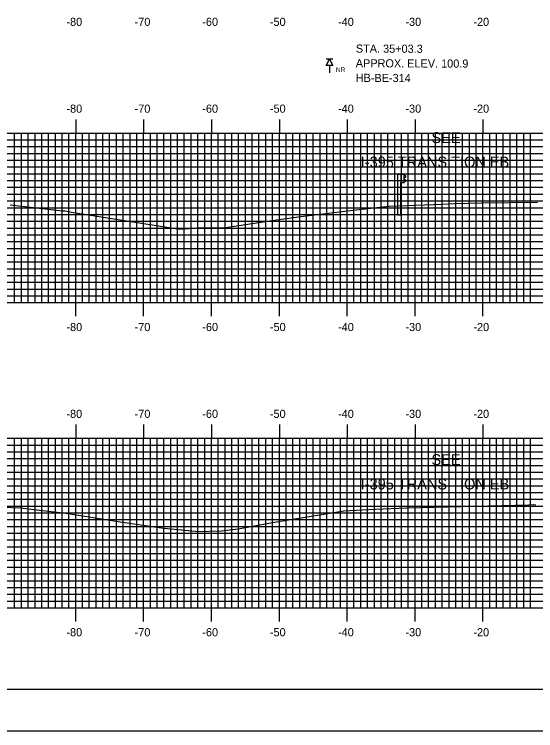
# Model space of a CAD drawing. Extents: x 842962 to 843305, y 363538 to 363758.
# Drawn here: x 843038.9 to 843115.7, y 363537.6 to 363643.2 of the extents above; entities that cross this region are included whole.
import ezdxf

# ---------------------------------------------------------------- set-up
doc = ezdxf.new("R2010")
doc.units = 0
for name, color, linetype in [('ANNOTATION', 7, 'Continuous'), ('BORDER', 7, 'Continuous'), ('BORING - NO REFUSAL', 7, 'Continuous'), ('H_V ANNOTATION', 7, 'Continuous'), ('M_Guardrail', 7, 'Continuous'), ('M_Roadway_Centerline', 7, 'Continuous'), ('MAJOR', 7, 'Continuous'), ('MINOR', 7, 'Continuous'), ('PLOT BOUNDARY', 7, 'Continuous'), ('S_Roadway_Centerline', 7, 'Continuous')]:
    doc.layers.add(name, color=color, linetype=linetype)

msp = doc.modelspace()

# ---------------------------------------------------------------- linework, layer by layer
at = {"layer": 'BORDER'}
msp.add_lwpolyline([(842978.31, 363543.72), (843298.31, 363543.72), (843298.31, 363753.72), (842978.31, 363753.72)], close=True, dxfattribs=at)
at = {"layer": 'BORING - NO REFUSAL'}
for p, q in [((843085.79, 363636.62), (843084.83, 363636.62)), ((843085.31, 363635.66), (843085.31, 363634.6))]:
    msp.add_line(p, q, dxfattribs=at)
msp.add_lwpolyline([(843085.31, 363636.62), (843085.79, 363635.66), (843084.83, 363635.66)], close=True, dxfattribs=at)
at = {"layer": 'M_Guardrail'}
for p, q in [((843095.3, 363619.6), (843095.3, 363613.6)), ((843095.79, 363619.6), (843095.3, 363619.6)), ((843096.28, 363619.6), (843095.79, 363619.6)), ((843095.79, 363619.6), (843095.79, 363618.44)), ((843096.28, 363618.44), (843096.28, 363619.6)), ((843096.28, 363619.53), (843096.37, 363619.52)), ((843096.53, 363619.27), (843096.33, 363619.13)), ((843096.38, 363619.51), (843096.53, 363619.41)), ((843095.79, 363613.6), (843095.79, 363618.44)), ((843095.79, 363618.44), (843096.28, 363618.44)), ((843096.37, 363618.53), (843096.28, 363618.51)), ((843096.3, 363619.07), (843096.3, 363618.98)), ((843096.33, 363618.91), (843096.53, 363618.78)), ((843096.53, 363618.63), (843096.38, 363618.53)), ((843095.79, 363613.6), (843095.3, 363613.6))]:
    msp.add_line(p, q, dxfattribs=at)
for centre, major_axis, start_param, end_param in [((843096.38, 363619.07), (-0.0789, 0), 5.323254, 6.283185), ((843096.36, 363619.48), (0.0417, 0), 0.959931, 1.396263), ((843096.48, 363619.34), (0.0877, 0), 5.323254, 7.243116), ((843096.38, 363618.98), (-0.0789, 0), 6.283185, 7.243116), ((843096.36, 363618.57), (0.0417, 0), 4.886922, 5.323254), ((843096.48, 363618.7), (0.0877, 0), 5.323254, 7.243116)]:
    msp.add_ellipse(centre, major_axis=major_axis, ratio=0.995501, start_param=start_param, end_param=end_param, dxfattribs=at)
at = {"layer": 'MAJOR'}
for p, q in [((843047.91, 363627.73), (843047.91, 363625.72)), ((843057.91, 363627.73), (843057.91, 363625.72)), ((843067.91, 363627.73), (843067.91, 363625.72)), ((843077.91, 363627.73), (843077.91, 363625.72)), ((843087.91, 363627.73), (843087.91, 363625.72)), ((843097.91, 363627.73), (843097.91, 363625.72)), ((843107.91, 363627.73), (843107.91, 363625.72)), ((842987.91, 363625.72), (843267.91, 363625.72)), ((842987.91, 363625.72), (843267.91, 363625.72)), ((843047.91, 363600.72), (843047.91, 363625.72)), ((843057.91, 363600.72), (843057.91, 363625.72)), ((843067.91, 363600.72), (843067.91, 363625.72)), ((843077.91, 363600.72), (843077.91, 363625.72)), ((843087.91, 363600.72), (843087.91, 363625.72)), ((843097.91, 363600.72), (843097.91, 363625.72)), ((843107.91, 363600.72), (843107.91, 363625.72)), ((842987.91, 363620.72), (843267.91, 363620.72)), ((842987.91, 363615.72), (843267.91, 363615.72)), ((842987.91, 363610.72), (843267.91, 363610.72)), ((842987.91, 363605.72), (843267.91, 363605.72)), ((842987.91, 363600.72), (843267.91, 363600.72)), ((842987.91, 363600.72), (843267.91, 363600.72)), ((843047.91, 363598.72), (843047.91, 363600.72)), ((843057.91, 363598.72), (843057.91, 363600.72)), ((843067.91, 363598.72), (843067.91, 363600.72)), ((843077.91, 363598.72), (843077.91, 363600.72)), ((843087.91, 363598.72), (843087.91, 363600.72)), ((843097.91, 363598.72), (843097.91, 363600.72)), ((843107.91, 363598.72), (843107.91, 363600.72)), ((843047.91, 363582.73), (843047.91, 363580.72)), ((843057.91, 363582.73), (843057.91, 363580.72)), ((843067.91, 363582.73), (843067.91, 363580.72)), ((843077.91, 363582.73), (843077.91, 363580.72)), ((843087.91, 363582.73), (843087.91, 363580.72)), ((843097.91, 363582.73), (843097.91, 363580.72)), ((843107.91, 363582.73), (843107.91, 363580.72)), ((842987.91, 363580.72), (843267.91, 363580.72)), ((842987.91, 363580.72), (843267.91, 363580.72)), ((843047.91, 363555.72), (843047.91, 363580.72)), ((843057.91, 363555.72), (843057.91, 363580.72)), ((843067.91, 363555.72), (843067.91, 363580.72)), ((843077.91, 363555.72), (843077.91, 363580.72)), ((843087.91, 363555.72), (843087.91, 363580.72)), ((843097.91, 363555.72), (843097.91, 363580.72)), ((843107.91, 363555.72), (843107.91, 363580.72)), ((842987.91, 363575.72), (843267.91, 363575.72)), ((842987.91, 363570.72), (843267.91, 363570.72)), ((842987.91, 363565.72), (843267.91, 363565.72)), ((842987.91, 363560.72), (843267.91, 363560.72)), ((842987.91, 363555.72), (843267.91, 363555.72)), ((842987.91, 363555.72), (843267.91, 363555.72)), ((843047.91, 363553.72), (843047.91, 363555.72)), ((843057.91, 363553.72), (843057.91, 363555.72)), ((843067.91, 363553.72), (843067.91, 363555.72)), ((843077.91, 363553.72), (843077.91, 363555.72)), ((843087.91, 363553.72), (843087.91, 363555.72)), ((843097.91, 363553.72), (843097.91, 363555.72)), ((843107.91, 363553.72), (843107.91, 363555.72))]:
    msp.add_line(p, q, dxfattribs=at)
at = {"layer": 'MINOR'}
for p, q in [((843038.91, 363600.72), (843038.91, 363625.72)), ((843039.91, 363600.72), (843039.91, 363625.72)), ((843040.91, 363600.72), (843040.91, 363625.72)), ((843041.91, 363600.72), (843041.91, 363625.72)), ((843042.91, 363600.72), (843042.91, 363625.72)), ((843043.91, 363600.72), (843043.91, 363625.72)), ((843044.91, 363600.72), (843044.91, 363625.72)), ((843045.91, 363600.72), (843045.91, 363625.72)), ((843046.91, 363600.72), (843046.91, 363625.72)), ((843048.91, 363600.72), (843048.91, 363625.72)), ((843049.91, 363600.72), (843049.91, 363625.72)), ((843050.91, 363600.72), (843050.91, 363625.72)), ((843051.91, 363600.72), (843051.91, 363625.72)), ((843052.91, 363600.72), (843052.91, 363625.72)), ((843053.91, 363600.72), (843053.91, 363625.72)), ((843054.91, 363600.72), (843054.91, 363625.72)), ((843055.91, 363600.72), (843055.91, 363625.72)), ((843056.91, 363600.72), (843056.91, 363625.72)), ((843058.91, 363600.72), (843058.91, 363625.72)), ((843059.91, 363600.72), (843059.91, 363625.72)), ((843060.91, 363600.72), (843060.91, 363625.72)), ((843061.91, 363600.72), (843061.91, 363625.72)), ((843062.91, 363600.72), (843062.91, 363625.72)), ((843063.91, 363600.72), (843063.91, 363625.72)), ((843064.91, 363600.72), (843064.91, 363625.72)), ((843065.91, 363600.72), (843065.91, 363625.72)), ((843066.91, 363600.72), (843066.91, 363625.72)), ((843068.91, 363600.72), (843068.91, 363625.72)), ((843069.91, 363600.72), (843069.91, 363625.72)), ((843070.91, 363600.72), (843070.91, 363625.72)), ((843071.91, 363600.72), (843071.91, 363625.72)), ((843072.91, 363600.72), (843072.91, 363625.72)), ((843073.91, 363600.72), (843073.91, 363625.72)), ((843074.91, 363600.72), (843074.91, 363625.72)), ((843075.91, 363600.72), (843075.91, 363625.72)), ((843076.91, 363600.72), (843076.91, 363625.72)), ((843078.91, 363600.72), (843078.91, 363625.72)), ((843079.91, 363600.72), (843079.91, 363625.72)), ((843080.91, 363600.72), (843080.91, 363625.72)), ((843081.91, 363600.72), (843081.91, 363625.72)), ((843082.91, 363600.72), (843082.91, 363625.72)), ((843083.91, 363600.72), (843083.91, 363625.72)), ((843084.91, 363600.72), (843084.91, 363625.72)), ((843085.91, 363600.72), (843085.91, 363625.72)), ((843086.91, 363600.72), (843086.91, 363625.72)), ((843088.91, 363600.72), (843088.91, 363625.72)), ((843089.91, 363600.72), (843089.91, 363625.72)), ((843090.91, 363600.72), (843090.91, 363625.72)), ((843091.91, 363600.72), (843091.91, 363625.72)), ((843092.91, 363600.72), (843092.91, 363625.72)), ((843093.91, 363600.72), (843093.91, 363625.72)), ((843094.91, 363600.72), (843094.91, 363625.72)), ((843095.91, 363600.72), (843095.91, 363625.72)), ((843096.91, 363600.72), (843096.91, 363625.72)), ((843098.91, 363600.72), (843098.91, 363625.72)), ((843099.91, 363600.72), (843099.91, 363625.72)), ((843100.91, 363600.72), (843100.91, 363625.72)), ((843101.91, 363600.72), (843101.91, 363625.72)), ((843102.91, 363600.72), (843102.91, 363625.72)), ((843103.91, 363600.72), (843103.91, 363625.72)), ((843104.91, 363600.72), (843104.91, 363625.72)), ((843105.91, 363600.72), (843105.91, 363625.72)), ((843106.91, 363600.72), (843106.91, 363625.72)), ((843108.91, 363600.72), (843108.91, 363625.72)), ((843109.91, 363600.72), (843109.91, 363625.72)), ((843110.91, 363600.72), (843110.91, 363625.72)), ((843111.91, 363600.72), (843111.91, 363625.72)), ((843112.91, 363600.72), (843112.91, 363625.72)), ((843113.91, 363600.72), (843113.91, 363625.72)), ((843114.91, 363600.72), (843114.91, 363625.72)), ((842987.91, 363624.72), (843267.91, 363624.72)), ((842987.91, 363623.72), (843267.91, 363623.72)), ((842987.91, 363622.72), (843267.91, 363622.72)), ((842987.91, 363621.72), (843267.91, 363621.72)), ((842987.91, 363619.72), (843267.91, 363619.72)), ((842987.91, 363618.72), (843267.91, 363618.72)), ((842987.91, 363617.72), (843267.91, 363617.72)), ((842987.91, 363616.72), (843267.91, 363616.72)), ((842987.91, 363614.72), (843267.91, 363614.72)), ((842987.91, 363613.72), (843267.91, 363613.72)), ((842987.91, 363612.72), (843267.91, 363612.72)), ((842987.91, 363611.72), (843267.91, 363611.72)), ((842987.91, 363609.72), (843267.91, 363609.72)), ((842987.91, 363608.72), (843267.91, 363608.72)), ((842987.91, 363607.72), (843267.91, 363607.72)), ((842987.91, 363606.72), (843267.91, 363606.72)), ((842987.91, 363604.72), (843267.91, 363604.72)), ((842987.91, 363603.72), (843267.91, 363603.72)), ((842987.91, 363602.72), (843267.91, 363602.72)), ((842987.91, 363601.72), (843267.91, 363601.72)), ((843038.91, 363555.72), (843038.91, 363580.72)), ((843039.91, 363555.72), (843039.91, 363580.72)), ((843040.91, 363555.72), (843040.91, 363580.72)), ((843041.91, 363555.72), (843041.91, 363580.72)), ((843042.91, 363555.72), (843042.91, 363580.72)), ((843043.91, 363555.72), (843043.91, 363580.72)), ((843044.91, 363555.72), (843044.91, 363580.72)), ((843045.91, 363555.72), (843045.91, 363580.72)), ((843046.91, 363555.72), (843046.91, 363580.72)), ((843048.91, 363555.72), (843048.91, 363580.72)), ((843049.91, 363555.72), (843049.91, 363580.72)), ((843050.91, 363555.72), (843050.91, 363580.72)), ((843051.91, 363555.72), (843051.91, 363580.72)), ((843052.91, 363555.72), (843052.91, 363580.72)), ((843053.91, 363555.72), (843053.91, 363580.72)), ((843054.91, 363555.72), (843054.91, 363580.72)), ((843055.91, 363555.72), (843055.91, 363580.72)), ((843056.91, 363555.72), (843056.91, 363580.72)), ((843058.91, 363555.72), (843058.91, 363580.72)), ((843059.91, 363555.72), (843059.91, 363580.72)), ((843060.91, 363555.72), (843060.91, 363580.72)), ((843061.91, 363555.72), (843061.91, 363580.72)), ((843062.91, 363555.72), (843062.91, 363580.72)), ((843063.91, 363555.72), (843063.91, 363580.72)), ((843064.91, 363555.72), (843064.91, 363580.72)), ((843065.91, 363555.72), (843065.91, 363580.72)), ((843066.91, 363555.72), (843066.91, 363580.72)), ((843068.91, 363555.72), (843068.91, 363580.72)), ((843069.91, 363555.72), (843069.91, 363580.72)), ((843070.91, 363555.72), (843070.91, 363580.72)), ((843071.91, 363555.72), (843071.91, 363580.72)), ((843072.91, 363555.72), (843072.91, 363580.72)), ((843073.91, 363555.72), (843073.91, 363580.72)), ((843074.91, 363555.72), (843074.91, 363580.72)), ((843075.91, 363555.72), (843075.91, 363580.72)), ((843076.91, 363555.72), (843076.91, 363580.72)), ((843078.91, 363555.72), (843078.91, 363580.72)), ((843079.91, 363555.72), (843079.91, 363580.72)), ((843080.91, 363555.72), (843080.91, 363580.72)), ((843081.91, 363555.72), (843081.91, 363580.72)), ((843082.91, 363555.72), (843082.91, 363580.72)), ((843083.91, 363555.72), (843083.91, 363580.72)), ((843084.91, 363555.72), (843084.91, 363580.72)), ((843085.91, 363555.72), (843085.91, 363580.72)), ((843086.91, 363555.72), (843086.91, 363580.72)), ((843088.91, 363555.72), (843088.91, 363580.72)), ((843089.91, 363555.72), (843089.91, 363580.72)), ((843090.91, 363555.72), (843090.91, 363580.72)), ((843091.91, 363555.72), (843091.91, 363580.72)), ((843092.91, 363555.72), (843092.91, 363580.72)), ((843093.91, 363555.72), (843093.91, 363580.72)), ((843094.91, 363555.72), (843094.91, 363580.72)), ((843095.91, 363555.72), (843095.91, 363580.72)), ((843096.91, 363555.72), (843096.91, 363580.72)), ((843098.91, 363555.72), (843098.91, 363580.72)), ((843099.91, 363555.72), (843099.91, 363580.72)), ((843100.91, 363555.72), (843100.91, 363580.72)), ((843101.91, 363555.72), (843101.91, 363580.72)), ((843102.91, 363555.72), (843102.91, 363580.72)), ((843103.91, 363555.72), (843103.91, 363580.72)), ((843104.91, 363555.72), (843104.91, 363580.72)), ((843105.91, 363555.72), (843105.91, 363580.72)), ((843106.91, 363555.72), (843106.91, 363580.72)), ((843108.91, 363555.72), (843108.91, 363580.72)), ((843109.91, 363555.72), (843109.91, 363580.72)), ((843110.91, 363555.72), (843110.91, 363580.72)), ((843111.91, 363555.72), (843111.91, 363580.72)), ((843112.91, 363555.72), (843112.91, 363580.72)), ((843113.91, 363555.72), (843113.91, 363580.72)), ((843114.91, 363555.72), (843114.91, 363580.72)), ((842987.91, 363579.72), (843267.91, 363579.72)), ((842987.91, 363578.72), (843267.91, 363578.72)), ((842987.91, 363577.72), (843267.91, 363577.72)), ((842987.91, 363576.72), (843267.91, 363576.72)), ((842987.91, 363574.72), (843267.91, 363574.72)), ((842987.91, 363573.72), (843267.91, 363573.72)), ((842987.91, 363572.72), (843267.91, 363572.72)), ((842987.91, 363571.72), (843267.91, 363571.72)), ((842987.91, 363569.72), (843267.91, 363569.72)), ((842987.91, 363568.72), (843267.91, 363568.72)), ((842987.91, 363567.72), (843267.91, 363567.72)), ((842987.91, 363566.72), (843267.91, 363566.72)), ((842987.91, 363564.72), (843267.91, 363564.72)), ((842987.91, 363563.72), (843267.91, 363563.72)), ((842987.91, 363562.72), (843267.91, 363562.72)), ((842987.91, 363561.72), (843267.91, 363561.72)), ((842987.91, 363559.72), (843267.91, 363559.72)), ((842987.91, 363558.72), (843267.91, 363558.72)), ((842987.91, 363557.72), (843267.91, 363557.72)), ((842987.91, 363556.72), (843267.91, 363556.72))]:
    msp.add_line(p, q, dxfattribs=at)
at = {"layer": 'PLOT BOUNDARY'}
msp.add_lwpolyline([(842962.12, 363537.6), (843302.12, 363537.6), (843302.12, 363757.6), (842962.12, 363757.6)], close=True, dxfattribs=at)
at = {"layer": 'S_Roadway_Centerline'}
for points in [[(843038.27, 363615.12), (843045.97, 363614.27), (843046.33, 363614.23), (843047.28, 363614.05), (843062.93, 363611.58), (843064.05, 363611.62), (843065.82, 363611.73), (843069.96, 363611.8), (843077.83, 363612.96), (843081.45, 363613.48), (843083.95, 363613.76), (843088.8, 363614.34), (843094.02, 363614.95), (843101.95, 363615.25), (843103.71, 363615.32), (843107.74, 363615.42), (843115.93, 363615.54)], [(843034.51, 363570.66), (843039.76, 363570.47), (843041.75, 363570.21), (843046.46, 363569.68), (843054.44, 363568.41), (843060.88, 363567.47), (843065.58, 363567.03), (843065.81, 363566.98), (843069.41, 363567.09), (843071.84, 363567.37), (843076.92, 363568.3), (843087.41, 363570), (843092.01, 363570.26), (843096.68, 363570.47), (843114.63, 363570.92), (843115.37, 363570.93), (843115.43, 363570.93), (843115.7, 363570.92)]]:
    msp.add_lwpolyline(points, dxfattribs=at)

# ---------------------------------------------------------------- texts
at = {"layer": 'ANNOTATION'}
for s, p in [('SEE', (843100.33, 363624.25)), ('I-395 TRANSITION EB', (843089.91, 363620.65)), ('SEE', (843100.33, 363576.77)), ('I-395 TRANSITION EB', (843089.91, 363573.17))]:
    msp.add_text(s, height=1.6, dxfattribs=at).set_placement(p)
at = {"layer": 'BORING - NO REFUSAL'}
for s, p in [('STA. 35+03.3', (843089.18, 363637.58)), ('APPROX. ELEV. 100.9', (843089.17, 363635.42)), ('HB-BE-314', (843089.16, 363633.26))]:
    msp.add_text(s, height=1.2, rotation=359.8142, dxfattribs=at).set_placement(p)
msp.add_text('NR', height=0.7, dxfattribs=at).set_placement((843086.24, 363634.71))
at = {"layer": 'H_V ANNOTATION'}
for s, p in [('-80', (843046.54, 363641.52)), ('-70', (843056.59, 363641.52)), ('-60', (843066.56, 363641.52)), ('-50', (843076.52, 363641.52)), ('-40', (843086.56, 363641.52)), ('-30', (843096.49, 363641.52)), ('-20', (843106.5, 363641.52)), ('-80', (843046.54, 363628.72)), ('-70', (843056.59, 363628.72)), ('-60', (843066.56, 363628.72)), ('-50', (843076.52, 363628.72)), ('-40', (843086.56, 363628.72)), ('-30', (843096.49, 363628.72)), ('-20', (843106.5, 363628.72)), ('-80', (843046.54, 363596.52)), ('-70', (843056.59, 363596.52)), ('-60', (843066.56, 363596.52)), ('-50', (843076.52, 363596.52)), ('-40', (843086.56, 363596.52)), ('-30', (843096.49, 363596.52)), ('-20', (843106.5, 363596.52)), ('-80', (843046.54, 363583.72)), ('-70', (843056.59, 363583.72)), ('-60', (843066.56, 363583.72)), ('-50', (843076.52, 363583.72)), ('-40', (843086.56, 363583.72)), ('-30', (843096.49, 363583.72)), ('-20', (843106.5, 363583.72)), ('-80', (843046.54, 363551.52)), ('-70', (843056.59, 363551.52)), ('-60', (843066.56, 363551.52)), ('-50', (843076.52, 363551.52)), ('-40', (843086.56, 363551.52)), ('-30', (843096.49, 363551.52)), ('-20', (843106.5, 363551.52))]:
    msp.add_text(s, height=1.2, dxfattribs=at).set_placement(p)
at = {"layer": 'M_Roadway_Centerline'}
for s, p in [('C', (843115.43, 363570.93)), ('L', (843115.43, 363570.92))]:
    msp.add_text(s, height=0.0146, dxfattribs=at).set_placement(p)

doc.saveas('drawing.dxf')
